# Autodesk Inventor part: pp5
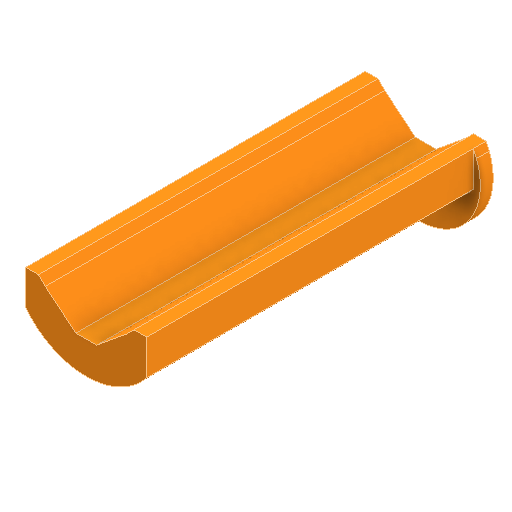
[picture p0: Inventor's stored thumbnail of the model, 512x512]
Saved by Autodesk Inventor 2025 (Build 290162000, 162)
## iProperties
Created: 2024-11
Part Number: pp5
Material: Generico
Document SubType Name: Modeling
Designer: R5800u
Density: 1 g/cm^3
Appearance: Arancione
Author: R5800u
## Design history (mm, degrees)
sketch "Schizzo1"
  geometry: L1 (-9, -7.159)-(-9, 7.159) reference; L2 (9, 7.159)-(9, -7.159) reference; L3 (-1.5, -6.539)-(-6, -2.83); L4 (-6, -2.83)-(-9, -2.83); L5 (0, 0)-(0, -11.612) reference; L6 (-1.5, -6.539)-(0, -6.539); L7 (6, -2.83)-(9, -2.83); L8 (1.5, -6.539)-(6, -2.83); L9 (1.5, -6.539)-(0, -6.539); C1 r 6 at (0, 0); A1 r 11.5 centre (0, 0) between (-9, -7.159) and (9, -7.159) reference; A2 r 11.5 centre (0, 0) between (9, 7.159) and (-9, 7.159) reference; 2 further points
  constraints: 14 end point, 3 symmetric about line, 2 perpendicular, 2 point on line, 2 vertical, 1 centre point, 1 coincident, 1 tangent
  dimensions: "d0" = 12 diameter of C1; "d2" = 1.5 distance of L3.start L6.end; "d3" = 3 distance of L3.end L4.end
extrude "Estrusione1" new body sketch "Schizzo1" distance "d4" = 50; taper "d5" = 0 deg
node "Piano di lavoro1"
sketch "Schizzo2"
  geometry: 3 further points
  constraints: 1 horizontal alignment, 2 other
hole "Foro1" sketch "Schizzo2" at (0, 10) diameter "d6" = 3.4; stored, may be unused: countersink angle "d10" = 90 deg, drill point angle "d12" = 0 deg; dims "d7" = 6, "d8" = 6.3, "d9" = 2, "d11" = 2.5
sketch "Schizzo3"
  geometry: L1 (9, -7.159)-(9, -2.83) reference; L2 (9, -2.83)-(6, -2.83) reference; L3 (6, -2.83)-(1.5, -6.539) reference; L4 (1.5, -6.539)-(-1.5, -6.539) reference; L5 (-1.5, -6.539)-(-6, -2.83) reference; L6 (-6, -2.83)-(-9, -2.83) reference; L7 (-9, -2.83)-(-9, -7.159) reference; A1 r 11.5 centre (0, 0) between (-9, -7.159) and (9, -7.159) reference; 1 further point
extrude "Estrusione2" cut sketch "Schizzo3" distance "d13" = 2; taper "d14" = 0 deg
sketch "Schizzo4"
  geometry: L1 (6, -2.83)-(9, -2.83) reference; L2 (1.5, -6.539)-(6, -2.83) reference; L3 (-1.5, -6.539)-(1.5, -6.539) reference; L4 (-6, -2.83)-(-1.5, -6.539) reference; L5 (-9, -2.83)-(-6, -2.83) reference; L6 (-9, -7.159)-(-9, -2.83) reference; L7 (9, -2.83)-(9, -7.159) reference; L8 (-8.9, -7.124)-(-8.9, -2.93); L9 (-8.9, -2.93)-(-6.036, -2.93); L10 (-6.036, -2.93)-(-1.536, -6.639); L11 (-1.536, -6.639)-(1.536, -6.639); L12 (1.536, -6.639)-(6.036, -2.93); L13 (6.036, -2.93)-(8.9, -2.93); L14 (8.9, -2.93)-(8.9, -7.124); A1 r 11.5 centre (0, 0) between (-9, -7.159) and (9, -7.159) reference; A2 r 11.4 centre (0, 0) between (-8.9, -7.124) and (8.9, -7.124); 1 further point
  constraints: 14 end point, 2 point on circle, 1 centre point, 7 other
  dimensions: "d15" = 0.1 radial gap between concentric circles of A1 A2
extrude "Estrusione3" cut sketch "Schizzo4" extent not by distance; stored distance "d16" = 0; taper "d17" = 0 deg
sketch "Schizzo5"
  geometry: L1 (0, 48)-(2.864, 48) reference; L2 (0, 0)-(0, 48) reference; L3 (2.864, 0)-(0, 0) reference; L4 (2.864, 0)-(2.864, 48) reference; L5 (14.936, 48)-(17.8, 48) reference; L6 (14.936, 0)-(14.936, 48) reference; L7 (17.8, 0)-(14.936, 0) reference; L8 (17.8, 0)-(17.8, 48) reference; 1 further point
extrude "Estrusione4" join sketch "Schizzo5" distance "d18" = 1; taper "d19" = 0 deg
chamfer "Smusso1" distance "d20" = 1; stored, may be unused: second distance "d21" = 2, angle "d22" = 45 deg
sketch "Schizzo6"
  geometry: L1 (-7.036, -1.93)-(-6.036, -2.93) reference; L2 (-8.9, -1.93)-(-7.036, -1.93) reference; L3 (-8.9, -1.93)-(-8.9, -7.124) reference; L4 (8.9, -7.124)-(8.9, -1.93) reference; L5 (7.036, -1.93)-(8.9, -1.93) reference; L6 (6.036, -2.93)-(7.036, -1.93) reference; L7 (6.036, -2.93)-(1.536, -6.639) reference; L8 (1.536, -6.639)-(-1.536, -6.639) reference; L9 (-1.536, -6.639)-(-6.036, -2.93) reference; L10 (5.02, -15.139)-(-5.02, -15.139); A1 r 11.4 centre (0, 0) between (-8.9, -7.124) and (8.9, -7.124) reference; A2 r 10 centre (0, -6.49) between (-8.9, -1.93) and (8.9, -1.93); 1 further point
  constraints: 4 point on circle, 2 end point, 1 centre point, 1 horizontal
  dimensions: "d23" = 10 radius of A2; "d26" = 8.5 distance between parallel lines of L8 L10
extrude "Estrusione5" join sketch "Schizzo6" distance "d24" = 2; taper "d25" = 0 deg
fillet "Raccordo1" dims "d27" = 9
chamfer "Smusso2" distance "d28" = 0.2; stored, may be unused: second distance "d29" = 2, angle "d30" = 45 deg
sketch "Schizzo7"
  geometry: L1 (0.936, -15.139)-(-0.936, -15.139) reference; L2 (8.9, -1.93)-(8.9, -7.124) reference; L3 (-8.9, -7.124)-(-8.9, -1.93) reference; A1 r 9 centre (-0.936, -6.139) between (-9.362, -2.975) and (-0.936, -15.139) reference; A2 r 9 centre (0.936, -6.139) between (0.936, -15.139) and (9.362, -2.975) reference; A3 r 10 centre (0, -6.49) between (9.362, -2.975) and (8.9, -1.93) reference; A4 r 11.4 centre (0, 0) between (-8.9, -7.124) and (8.9, -7.124) reference; A5 r 10 centre (0, -6.49) between (-8.9, -1.93) and (-9.362, -2.975) reference; 1 further point
extrude "Estrusione6" cut sketch "Schizzo7" distance "d31" = 0.1; taper "d32" = 0 deg
node "Solido1"
node "Riferimento1"
node "Riferimento2"
node "Riferimento3"
node "Riferimento4"
node "Riferimento5"
node "Linea chiusa proiettata1"
node "Linea chiusa proiettata2"
node "Linea chiusa proiettata3"
node "Linea chiusa proiettata4"
node "Linea chiusa proiettata5"
node "Linea chiusa proiettata6"
